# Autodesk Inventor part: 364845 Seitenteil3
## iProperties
Company: Hundt & Weber AG Schaltgeräte
Created: 2010-11
Part Number: 364845 Seitenteil3
Material: 1.0120
Document SubType Name: Modeling
Designer: I.Baliuc
Manufacturer: Standard
Standards Organization: Custom
Description: Seitenteil, Trenner
Cost Center: 5,196 kg
Authority: 661896 mm^3
Density: 7.85 g/cm^3
HalbzeugNorm: DIN 174
Zweck: HSLT / HSE - Standardseite
Abmessung: Fl. 120x12-170
SaveDate: 2006-10-28
SaveTime: 20:23
TotalMass: 5,196 kg
TotalVolume: 661896 mm^3
Author: AHausen
Revision Number: 364845
Keywords: 380125
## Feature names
1. Extrusion2
2. Bohrung_Ø13 [Hole]
3. Bohrung2 [Hole]
4. Bohrung3 [Hole]
5. Bohrung_M8_01 [Hole]
6. Bohrung_M8_02 [Hole]
7. Bohrung_M6 [Hole]
8. Bohrung_M5 [Hole]
9. Neue Bohrung (zusätzlich) [Rectangular Pattern]
